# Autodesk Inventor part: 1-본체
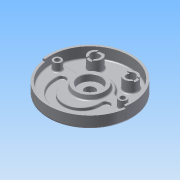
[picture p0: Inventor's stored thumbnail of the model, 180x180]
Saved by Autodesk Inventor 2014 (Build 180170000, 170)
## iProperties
Created: 2015-06
Part Number: 1-본체
Material: 알루미늄 6061
Document SubType Name: Modeling
Designer: Administrator
Density: 2.71 g/cm^3
Appearance: 알루미늄 - 평지
Mass: 1070.29 g
Surface Area: 1033.58 cm^2
Volume: 394.94 cm^3
Author: Administrator
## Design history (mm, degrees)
sketch "스케치1"
  geometry: C1 r 95 at (0, 0); 1 further point
  constraints: 1 centre point, 1 coincident
  dimensions: "d0" = 190 diameter of C1
extrude "돌출1" new body sketch "스케치1" distance "d1" = 32; taper "d2" = 0 deg
sketch "스케치2"
  geometry: L1 (-38.833, 16)-(-88.566, 16); L2 (38.833, 16)-(88.566, 16); C1 r 95 at (0, 0) reference; A1 r 90 centre (0, 0) between (-88.566, 16) and (88.566, 16); A2 r 42 centre (0, 0) between (-38.833, 16) and (38.833, 16)
  constraints: 4 end point, 4 point on circle, 2 centre point, 2 coincident, 2 collinear, 1 horizontal
  dimensions: "d3" = 180 diameter of A1; "d4" = 84 diameter of A2; "d5" = 16 distance from line of L2 C1.centre
extrude "돌출2" cut sketch "스케치2" distance "d6" = 25; taper "d7" = 0 deg
extrude "돌출3" cut sketch "스케치2" distance "d8" = 18; taper "d9" = 0 deg
sketch "스케치3"
  geometry: C1 r 35 at (0, 0); A1 r 90 centre (0, 0) between (-88.566, 16) and (88.566, 16) reference
  constraints: 1 centre point, 1 coincident
  dimensions: "d10" = 70 diameter of C1
extrude "돌출4" join sketch "스케치3" distance "d11" = 10; taper "d12" = -10 deg
sketch "스케치4"
  geometry: L1 (38.833, 16)-(88.566, 16) reference; L2 (41, -19)-(59, -19); L3 (-59, -19)-(-41, -19); L4 (-59, -19)-(-59, -14); L5 (-41, -14)-(-41, -19); L6 (41, -19)-(41, -14); L7 (59, -14)-(59, -19); C1 r 35 at (0, 0) reference; A1 r 41 centre (0, -19) between (-41, -19) and (41, -19); A2 r 59 centre (0, -19) between (-59, -19) and (59, -19); A3 r 9 centre (-50, -14) between (-41, -14) and (-59, -14); A4 r 9 centre (50, -14) between (59, -14) and (41, -14)
  constraints: 12 end point, 9 point on circle, 8 tangent, 4 centre point, 4 parallel, 3 horizontal alignment, 1 coincident, 1 collinear, 1 perpendicular, 1 vertical alignment
  dimensions: "d15" = 59 radius of A2; "d16" = 41 radius of A1; "d17" = 19 distance of A2.centre C1.centre; "d18" = 5 vertical distance of L2.end A4.centre
extrude "돌출5" cut sketch "스케치4" distance "d19" = 7; taper "d20" = 0 deg
sketch "스케치5"
  geometry: C1 r 35 at (0, 0) reference; C2 r 9 at (-74, 0); C3 r 9 at (74, 0)
  constraints: 2 centre point, 2 horizontal alignment, 1 equal radius
  dimensions: "d21" = 18 diameter of C2; "d22" = 74 distance of C1.centre C2.centre; "d23" = 74 distance of C1.centre C3.centre (= d22)
extrude "돌출6" join sketch "스케치5" distance "d24" = 18; taper "d25" = 0 deg
sketch "스케치6"
  geometry: C1 r 15 at (-40, 52); C2 r 15 at (40, 52); A1 r 42 centre (0, 0) between (38.833, 16) and (-38.833, 16) reference
  constraints: 2 centre point, 1 equal radius, 1 horizontal alignment
  dimensions: "d26" = 30 diameter of C1; "d27" = 40 horizontal distance of A1.centre C1.centre; "d28" = 40 horizontal distance of A1.centre C2.centre (= d27); "d29" = 52 vertical distance of C2.centre A1.centre
extrude "돌출7" join sketch "스케치6" distance "d30" = 25; taper "d31" = 0 deg
hole "구멍1" diameter "d34" = 20; stored, may be unused: countersink angle "d38" = 90 deg, drill point angle "d40" = 118 deg; dims "d32" = 10, "d33" = 10, "d35" = 6, "d36" = 4, "d37" = 2, "d39" = 8
hole "구멍2" diameter "d43" = 20; stored, may be unused: countersink angle "d47" = 90 deg, drill point angle "d49" = 118 deg; dims "d41" = 10, "d42" = 10, "d44" = 6, "d45" = 4, "d46" = 2, "d48" = 8
sketch "스케치7"
  geometry: C1 r 9 at (-74, 0) reference; C2 r 9 at (74, 0) reference; 2 further points
  constraints: 2 coincident
hole "구멍3" sketch "스케치7" at (-74, 0), (74, 0) diameter "d50" = 11; stored, may be unused: countersink angle "d54" = 90 deg, drill point angle "d56" = 118 deg; dims "d51" = 6, "d52" = 18, "d53" = 11, "d55" = 8
sketch "스케치8"
  geometry: C1 r 95 at (0, 0) reference; C2 r 26 at (0, 0)
  constraints: 1 centre point, 1 coincident
  dimensions: "d57" = 52 diameter of C2
extrude "돌출8" join sketch "스케치8" distance "d58" = 12; taper "d59" = -15 deg
hole "구멍4" diameter "d62" = 23; stored, may be unused: countersink angle "d66" = 90 deg, drill point angle "d68" = 118 deg; dims "d60" = 10, "d61" = 10, "d63" = 6, "d64" = 50, "d65" = 15, "d67" = 8
sketch "스케치9"
  geometry: C1 r 95 at (0, 0) reference; C2 r 68 at (0, 0)
  constraints: 1 centre point, 1 coincident, 1 other
  dimensions: "d69" = 136 diameter of C2
feature "엠보싱1" sketch "스케치9" dims "d70" = 0.5, "d71" = 0
sketch "스케치10"
  geometry: L1 (0, 0)-(-95, 0); L2 (0, 0)-(95, 0); L3 (0, 0)-(89.124, -12.526); L4 (0, 0)-(-89.124, -12.526); L5 (-89.124, -12.526)-(-94.075, -13.221); L6 (89.124, -12.526)-(94.075, -13.221); A1 r 95 centre (0, 0) between (-95, 0) and (95, 0) reference; A2 r 90 centre (0, 0) between (89.124, -12.526) and (-89.124, -12.526) reference
  constraints: 12 end point, 6 point on circle, 3 collinear, 1 horizontal
  dimensions: "d72" = 8 deg angle of L3 L2; "d73" = 8 deg angle of L1 L4
extrude "돌출9" cut sketch "스케치10" distance "d74" = 5; taper "d75" = 0 deg
sketch "스케치11"
  geometry: L1 (-6, -19)-(6, -19); L2 (6, -19)-(6, 19); L3 (6, 19)-(-6, 19); L4 (-6, 19)-(-6, -19); L5 (-6, -19)-(6, 19); L6 (6, -19)-(-6, 19); L7 (99, 6)-(61, 6); L8 (61, 6)-(61, -6); L9 (61, -6)-(99, -6); L10 (99, -6)-(99, 6); L11 (99, 6)-(61, -6); L12 (61, 6)-(99, -6); C1 r 15 at (0, 0) reference; C2 r 10 at (80, 0) reference; C3 r 15 at (80, 0) reference; 1 further point
  constraints: 24 end point, 4 midpoint, 4 parallel, 2 horizontal, 2 perpendicular
  dimensions: "d86" = 12 distance of L7.end L8.end; "d87" = 38 distance of L7.start L7.end; "d88" = 38 distance of L1.end L2.end; "d89" = 12 distance of L2.end L3.end
extrude "돌출10" cut sketch "스케치11" distance "d90" = 3; taper "d91" = 0 deg
chamfer "모따기1" distance "d76" = 1; stored, may be unused: second distance "d77" = 2, angle "d78" = 45 deg
fillet "모깎기1" dims "d79" = 0.3, "d80" = 10, "d81" = 5, "d85" = 1
fillet "모깎기2" dims "d82" = 3, "d83" = 3, "d84" = 3
node "솔리드1"
node "투영된 루프1"
